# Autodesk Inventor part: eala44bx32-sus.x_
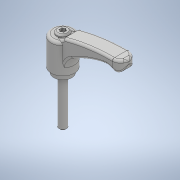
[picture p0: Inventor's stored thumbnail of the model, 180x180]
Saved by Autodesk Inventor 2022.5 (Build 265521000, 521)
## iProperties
Created: 2018-05
Part Number: eala44bx32-sus.x_
Material: 一般
Document SubType Name: Modeling
Designer: imaocorp
Density: 1 g/cm^3
Appearance: 既定
Sending System: SOLIDWORKS 2016-2016286
MC: AMD64
MC_MODEL: AMD64 Family 21 Model 2 Stepping 0, AuthenticAMD
OS: Windows_NT
FRU: Parasolid Version 28.0, build 224,  7-29-2016
FORMAT: text
GUISE: transmit
KEY: eala44bx32-sus
FILE: eala44bx32-sus.x_t
DATE: Fri May 18 11:28:25 2018
Author: imaocorp
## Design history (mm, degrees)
feature "Base1"
node "ソリッド1"
